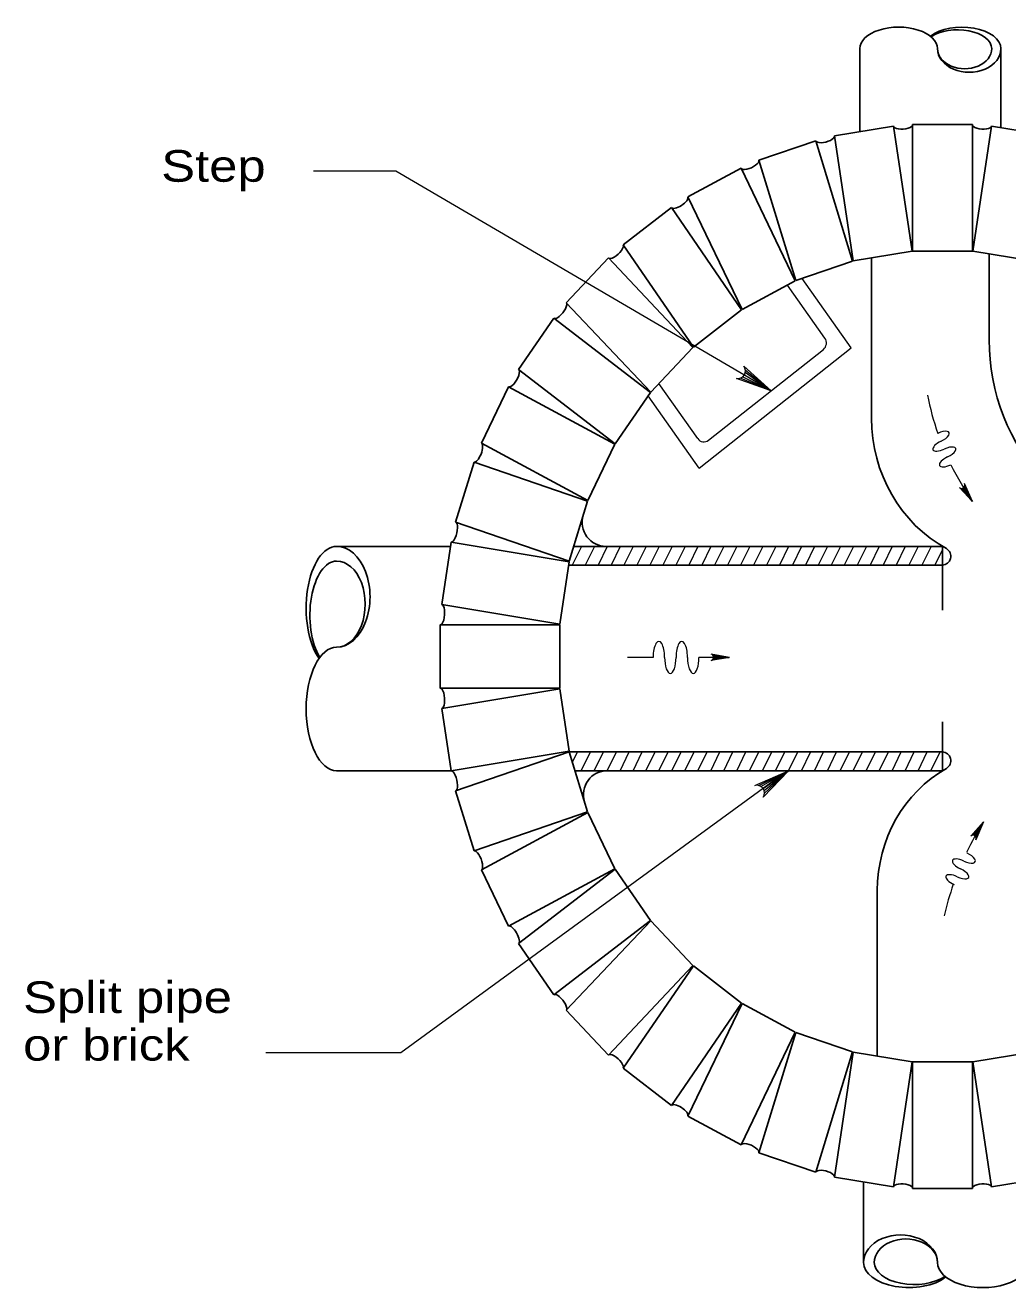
# Model space of a CAD drawing. Extents: x 1083.1 to 1117.1, y 697.4 to 741.4.
# Drawn here: x 1104.71 to 1109.55, y 723.01 to 729.25 of the extents above; entities that cross this region are included whole.
import ezdxf

# ---------------------------------------------------------------- set-up
doc = ezdxf.new("R2010")
doc.units = 0
doc.header["$LTSCALE"] = 0.062
doc.layers.add('1', color=7, linetype='Continuous', lineweight=13)

msp = doc.modelspace()

# ---------------------------------------------------------------- linework, layer by layer
at = {"layer": '1', "lineweight": 25}
for p, q in [((1108.823, 729.13192), (1108.823, 728.72233)), ((1109.51925, 729.13192), (1109.51925, 728.74242)), ((1109.08383, 728.758), (1109.08383, 728.13417)), ((1109.08383, 728.758), (1109.37842, 728.758)), ((1109.37842, 728.758), (1109.37842, 728.13417)), ((1108.69808, 728.70133), (1108.98908, 728.75017)), ((1108.69808, 728.70133), (1108.79025, 728.08517)), ((1108.98908, 728.75017), (1109.08125, 728.134)), ((1109.47317, 728.75017), (1109.381, 728.134)), ((1109.47317, 728.75017), (1109.76417, 728.70133)), ((1108.3255, 728.5815), (1108.60567, 728.67783)), ((1108.60567, 728.67783), (1108.78775, 728.08458)), ((1108.3255, 728.5815), (1108.50758, 727.98817)), ((1107.97517, 728.40133), (1108.23767, 728.543)), ((1108.23767, 728.543), (1108.50517, 727.98708)), ((1107.97517, 728.40133), (1108.24267, 727.8455)), ((1107.65583, 728.16542), (1107.89417, 728.34875)), ((1107.89417, 728.34875), (1108.2405, 727.84408)), ((1107.65583, 728.16542), (1108.00217, 727.66075)), ((1108.79025, 728.08517), (1109.08125, 728.134)), ((1109.08383, 728.13417), (1109.37842, 728.13417)), ((1109.381, 728.134), (1109.67192, 728.08517)), ((1107.37517, 727.87958), (1107.58358, 728.10008)), ((1107.58358, 728.10008), (1108.00017, 727.659)), ((1108.50758, 727.98817), (1108.78775, 728.08458)), ((1108.88108, 728.10042), (1108.88108, 727.30992)), ((1109.46125, 728.1205), (1109.46125, 727.69675)), ((1108.24267, 727.8455), (1108.50517, 727.98708)), ((1107.37517, 727.87958), (1107.79183, 727.43842)), ((1108.00217, 727.66075), (1108.2405, 727.84408)), ((1107.14033, 727.55067), (1107.3135, 727.80308)), ((1107.3135, 727.80308), (1107.79017, 727.43633)), ((1107.79183, 727.43842), (1108.00017, 727.659)), ((1107.14033, 727.55067), (1107.617, 727.184)), ((1106.95692, 727.187), (1107.09067, 727.46492)), ((1107.09067, 727.46492), (1107.61567, 727.18167)), ((1107.617, 727.184), (1107.79017, 727.43633)), ((1106.95692, 727.187), (1107.48192, 726.90375)), ((1107.48192, 726.90375), (1107.61567, 727.18167)), ((1106.8295, 726.79742), (1106.92058, 727.09408)), ((1106.92058, 727.09408), (1107.48092, 726.90125)), ((1107.38992, 726.60467), (1107.48092, 726.90125)), ((1106.8295, 726.79742), (1107.38992, 726.60467)), ((1106.76125, 726.3915), (1106.80733, 726.69958)), ((1106.80733, 726.69958), (1107.38933, 726.602)), ((1106.243, 726.678), (1106.80408, 726.678)), ((1107.41242, 726.678), (1109.23108, 726.678)), ((1109.23108, 726.678), (1109.23108, 726.36308)), ((1107.34325, 726.29392), (1107.38933, 726.602)), ((1107.38692, 726.58583), (1109.23108, 726.58583)), ((1106.76125, 726.3915), (1107.34325, 726.29392)), ((1106.75375, 725.97933), (1106.75375, 726.29125)), ((1106.75375, 726.29125), (1107.343, 726.29125)), ((1107.343, 725.97933), (1107.343, 726.29125)), ((1106.75375, 725.97933), (1107.343, 725.97933)), ((1106.76125, 725.879), (1107.34325, 725.97658)), ((1107.38933, 725.6685), (1107.34325, 725.97658)), ((1106.80733, 725.57092), (1106.76125, 725.879)), ((1109.23108, 725.81317), (1109.23108, 725.57233)), ((1106.80733, 725.57092), (1107.38933, 725.6685)), ((1106.8295, 725.47308), (1107.38992, 725.66583)), ((1107.48092, 725.36925), (1107.38992, 725.66583)), ((1107.39033, 725.6645), (1108.83858, 725.6645)), ((1108.83858, 725.6645), (1109.23108, 725.6645)), ((1106.243, 725.57233), (1106.80708, 725.57233)), ((1107.41858, 725.57233), (1108.83858, 725.57233)), ((1108.83858, 725.57233), (1109.23108, 725.57233)), ((1106.92058, 725.17642), (1106.8295, 725.47308)), ((1106.92058, 725.17642), (1107.48092, 725.36925)), ((1106.95692, 725.0835), (1107.48192, 725.36675)), ((1107.61567, 725.08883), (1107.48192, 725.36675)), ((1107.09067, 724.80558), (1106.95692, 725.0835)), ((1107.09067, 724.80558), (1107.61567, 725.08883)), ((1107.14033, 724.71983), (1107.617, 725.0865)), ((1107.79017, 724.83417), (1107.617, 725.0865)), ((1108.90933, 724.16533), (1108.90933, 724.98117)), ((1107.3135, 724.46742), (1107.79017, 724.83417)), ((1107.37525, 724.39092), (1107.79183, 724.83208)), ((1108.00017, 724.6115), (1107.79183, 724.83208)), ((1107.3135, 724.46742), (1107.14033, 724.71983)), ((1107.5835, 724.17042), (1108.00017, 724.6115)), ((1107.65583, 724.10508), (1108.00217, 724.60975)), ((1108.2405, 724.42642), (1108.00217, 724.60975)), ((1107.89417, 723.92175), (1108.2405, 724.42642)), ((1107.97517, 723.86917), (1108.24267, 724.425)), ((1108.50517, 724.28342), (1108.24267, 724.425)), ((1107.5835, 724.17042), (1107.37525, 724.39092)), ((1108.23767, 723.7275), (1108.50517, 724.28342)), ((1108.3255, 723.68908), (1108.50758, 724.28233)), ((1108.78775, 724.18592), (1108.50758, 724.28233)), ((1108.60567, 723.59267), (1108.78775, 724.18592)), ((1108.69808, 723.56917), (1108.79025, 724.18533)), ((1109.08125, 724.1365), (1108.79025, 724.18533)), ((1109.672, 724.18533), (1109.381, 724.1365)), ((1107.89417, 723.92175), (1107.65583, 724.10508)), ((1108.98908, 723.52042), (1109.08125, 724.1365)), ((1109.37842, 724.13633), (1109.08383, 724.13633)), ((1109.08383, 723.5125), (1109.08383, 724.13633)), ((1109.37842, 723.5125), (1109.37842, 724.13633)), ((1109.47317, 723.52042), (1109.381, 724.1365)), ((1108.23767, 723.7275), (1107.97517, 723.86917)), ((1108.60567, 723.59267), (1108.3255, 723.68908)), ((1108.98908, 723.52042), (1108.69808, 723.56917)), ((1108.84167, 723.148), (1108.84167, 723.54508)), ((1109.76417, 723.56917), (1109.47317, 723.52042)), ((1109.37842, 723.5125), (1109.08383, 723.5125))]:
    msp.add_line(p, q, dxfattribs=at)
at = {"layer": '1'}
for p, q in [((1108.651, 727.70508), (1108.46667, 727.96633)), ((1108.78117, 727.6565), (1108.5395, 727.99917)), ((1108.03075, 727.06333), (1108.78117, 727.6565)), ((1108.07667, 727.20108), (1108.64333, 727.64908)), ((1108.24642, 727.5145), (1108.38533, 727.44508)), ((1108.25367, 727.52333), (1108.38533, 727.44508)), ((1108.25858, 727.54925), (1108.38533, 727.44508)), ((1108.25858, 727.53717), (1108.38533, 727.44508)), ((1108.02383, 727.20925), (1107.83208, 727.481)), ((1108.23608, 727.50775), (1108.38533, 727.44508)), ((1108.03075, 727.06333), (1107.77908, 727.42017)), ((1109.37925, 726.89983), (1109.31483, 726.96917)), ((1109.37925, 726.89983), (1109.325, 726.96425)), ((1109.33142, 726.96533), (1109.37817, 726.901)), ((1109.37925, 726.89983), (1109.33758, 726.97017)), ((1109.37925, 726.89983), (1109.3395, 726.9875)), ((1109.37925, 726.89983), (1109.34033, 726.97533)), ((1109.37925, 726.89983), (1109.34042, 726.97517)), ((1107.45, 726.678), (1107.40467, 726.58583)), ((1107.51392, 726.678), (1107.4685, 726.58583)), ((1107.57783, 726.678), (1107.53242, 726.58583)), ((1107.64167, 726.678), (1107.59633, 726.58583)), ((1107.70558, 726.678), (1107.66017, 726.58583)), ((1107.7695, 726.678), (1107.72408, 726.58583)), ((1107.83333, 726.678), (1107.78792, 726.58583)), ((1107.89725, 726.678), (1107.85183, 726.58583)), ((1107.96108, 726.678), (1107.91575, 726.58583)), ((1108.025, 726.678), (1107.97958, 726.58583)), ((1108.08892, 726.678), (1108.0435, 726.58583)), ((1108.15275, 726.678), (1108.10733, 726.58583)), ((1108.21667, 726.678), (1108.17125, 726.58583)), ((1108.28058, 726.678), (1108.23517, 726.58583)), ((1108.34442, 726.678), (1108.299, 726.58583)), ((1108.40833, 726.678), (1108.36292, 726.58583)), ((1108.47217, 726.678), (1108.42683, 726.58583)), ((1108.53608, 726.678), (1108.49067, 726.58583)), ((1108.6, 726.678), (1108.55458, 726.58583)), ((1108.66383, 726.678), (1108.61842, 726.58583)), ((1108.72775, 726.678), (1108.68233, 726.58583)), ((1108.79167, 726.678), (1108.74625, 726.58583)), ((1108.8555, 726.678), (1108.81008, 726.58583)), ((1108.91942, 726.678), (1108.874, 726.58583)), ((1108.98325, 726.678), (1108.93783, 726.58583)), ((1109.04717, 726.678), (1109.00175, 726.58583)), ((1109.11108, 726.678), (1109.06567, 726.58583)), ((1109.17492, 726.678), (1109.1295, 726.58583)), ((1109.23108, 726.66233), (1109.19342, 726.58583)), ((1108.18042, 726.13083), (1108.08975, 726.14683)), ((1108.18042, 726.13083), (1108.09967, 726.1405)), ((1108.18042, 726.13083), (1108.09983, 726.1405)), ((1107.80383, 726.13083), (1107.67767, 726.13083)), ((1108.18042, 726.13083), (1108.03, 726.13083)), ((1108.18042, 726.13083), (1108.08975, 726.11483)), ((1108.18042, 726.13083), (1108.09942, 726.12083)), ((1108.18042, 726.13083), (1108.10208, 726.13517)), ((1108.10225, 726.127), (1108.17883, 726.13058)), ((1107.40583, 725.61383), (1107.43083, 725.6645)), ((1107.44925, 725.57233), (1107.49467, 725.6645)), ((1107.51317, 725.57233), (1107.55858, 725.6645)), ((1107.57708, 725.57233), (1107.62242, 725.6645)), ((1107.64092, 725.57233), (1107.68633, 725.6645)), ((1107.70483, 725.57233), (1107.75025, 725.6645)), ((1107.76867, 725.57233), (1107.81408, 725.6645)), ((1107.83258, 725.57233), (1107.878, 725.6645)), ((1107.8965, 725.57233), (1107.94192, 725.6645)), ((1107.96033, 725.57233), (1108.00575, 725.6645)), ((1108.02425, 725.57233), (1108.06967, 725.6645)), ((1108.08817, 725.57233), (1108.1335, 725.6645)), ((1108.152, 725.57233), (1108.19742, 725.6645)), ((1108.21592, 725.57233), (1108.26133, 725.6645)), ((1108.27975, 725.57233), (1108.32517, 725.6645)), ((1108.34367, 725.57233), (1108.38908, 725.6645)), ((1108.40758, 725.57233), (1108.45292, 725.6645)), ((1108.47142, 725.57233), (1108.51683, 725.6645)), ((1108.53533, 725.57233), (1108.5805, 725.664)), ((1108.59917, 725.57233), (1108.64458, 725.6645)), ((1108.66308, 725.57233), (1108.7085, 725.6645)), ((1108.727, 725.57233), (1108.77242, 725.6645)), ((1108.79083, 725.57233), (1108.83625, 725.6645)), ((1108.85475, 725.57233), (1108.90017, 725.6645)), ((1108.85475, 725.57233), (1108.89992, 725.664)), ((1108.91867, 725.57233), (1108.964, 725.6645)), ((1108.9825, 725.57233), (1109.02792, 725.6645)), ((1109.04642, 725.57233), (1109.09183, 725.6645)), ((1109.11033, 725.57233), (1109.15567, 725.6645)), ((1109.17417, 725.57233), (1109.21958, 725.6645)), ((1108.32458, 725.49933), (1108.47142, 725.57233)), ((1108.33558, 725.49442), (1108.47142, 725.57233)), ((1108.34617, 725.48425), (1108.47142, 725.57233)), ((1108.35133, 725.474), (1108.47142, 725.57233)), ((1108.35325, 725.46183), (1108.47142, 725.57233)), ((1109.4335, 725.32025), (1109.37092, 725.249)), ((1109.4335, 725.32025), (1109.38133, 725.25425)), ((1109.4335, 725.32025), (1109.3815, 725.25433)), ((1109.4335, 725.32025), (1109.38692, 725.25342)), ((1109.39342, 725.24908), (1109.43283, 725.31867)), ((1109.4335, 725.32025), (1109.39608, 725.23133)), ((1109.4335, 725.32025), (1109.39667, 725.24317))]:
    msp.add_line(p, q, dxfattribs=at)
for points in [[(1108.38533, 727.44508), (1106.53542, 728.528), (1106.12867, 728.528)], [(1108.25125, 727.566), (1108.38533, 727.44508), (1108.21508, 727.50508)], [(1108.446, 725.557), (1106.56008, 724.18133), (1105.8945, 724.18133)], [(1108.30625, 725.4995), (1108.47142, 725.57233), (1108.347, 725.44158)]]:
    msp.add_lwpolyline(points, dxfattribs=at)
for centre, start, end in [((1108.22084, 727.54282), 261.36559, 37.19171), ((1108.31498, 725.46228), 327.19941, 103.02554)]:
    msp.add_arc(centre, 0.0382, start, end, dxfattribs=at)
at = {"layer": '1', "lineweight": 25}
for centre, start, end in [((1107.57206, 726.79599), 162.93825, 270), ((1107.57826, 725.45434), 90, 197.06204)]:
    msp.add_arc(centre, 0.118, start, end, dxfattribs=at)
for centre, major_axis, ratio, start_param, end_param in [((1109.01477, 729.13189), (0.19174, 0), 0.553681, 0, 3.1415927), ((1109.32751, 729.13189), (0.19174, 0), 0.553681, 0, 2.5244674), ((1109.30532, 729.13189), (0.16853, 0), 0.553681, 0, 2.4601045), ((1109.34018, 729.13189), (0.13367, 0), 0.743645, 3.1415928, 6.2831855), ((1109.36288, 729.13189), (0.15637, 0), 0.743645, 3.1415928, 6.2831855), ((1109.03643, 728.75408), (0.04736, 0.00403), 0.392063, 3.1374537, 6.2790464), ((1109.42579, 728.75408), (0.04736, -0.00402), 0.392063, 3.1457278, 6.2873205), ((1108.65187, 728.68959), (0.04614, 0.01196), 0.389745, 3.1296802, 6.2712729), ((1108.28158, 728.56221), (0.04376, 0.01956), 0.385425, 3.1233154, 6.2649081), ((1107.93466, 728.37507), (0.04029, 0.02663), 0.37966, 3.1190216, 6.2606142), ((1107.61967, 728.13278), (0.03583, 0.033), 0.373134, 3.117142, 6.2587347), ((1107.34436, 727.8413), (0.03052, 0.03853), 0.366547, 3.1177098, 6.2593025), ((1110.39145, 727.69675), (0, 0.98483), 0.944544, 1.5707933, 3.1415918), ((1107.1155, 727.50782), (0.0245, 0.04308), 0.360527, 3.1205104, 6.2621031), ((1109.56493, 727.30989), (0, -0.72403), 0.944544, 4.7123884, 5.8053598), ((1106.93874, 727.14054), (0.01791, 0.04658), 0.355581, 3.1251606, 6.2667532), ((1106.81842, 726.7485), (0.01091, 0.04895), 0.352085, 3.1311777, 6.2727704), ((1106.243, 726.37349), (0, 0.30449), 0.493973, 6.2831853, 8.8076526), ((1106.243, 726.42966), (0, 0.24833), 0.663452, 3.1415925, 6.2831852), ((1109.23105, 726.629), (0, -0.04315), 0.944544, 0.0006242, 2.6457264), ((1106.243, 726.33825), (0, 0.26763), 0.493973, 6.2831853, 8.7432897), ((1106.243, 726.3936), (0, 0.21228), 0.663452, 3.1415925, 6.2831852), ((1106.75751, 726.34136), (0.00366, 0.05015), 0.350278, 3.1380288, 6.2796215), ((1106.243, 725.87683), (0, 0.30449), 0.493973, 6.2831853, 9.4247779), ((1106.75751, 725.92915), (-0.00367, 0.05015), 0.350278, 3.1451597, 6.2867524), ((1109.23107, 725.62151), (0, 0.04297), 0.944544, 3.6464672, 6.2827998), ((1109.55476, 724.98115), (0, 0.68332), 0.944544, 0.4905201, 1.5707908), ((1106.81842, 725.52201), (-0.01091, 0.04895), 0.352086, 3.1520106, 6.2936033), ((1106.93873, 725.12998), (-0.01791, 0.04658), 0.355583, 3.1580272, 6.2996199), ((1107.11549, 724.76269), (-0.0245, 0.04308), 0.360529, 3.1626767, 6.3042693), ((1107.34435, 724.42921), (-0.03053, 0.03852), 0.36655, 3.1654763, 6.307069), ((1107.61966, 724.13773), (-0.03584, 0.033), 0.373137, 3.166043, 6.3076357), ((1107.93466, 723.89543), (-0.04029, 0.02663), 0.379662, 3.1641623, 6.3057549), ((1108.28157, 723.70829), (-0.04376, 0.01956), 0.385427, 3.1598674, 6.3014601), ((1108.65187, 723.58091), (-0.04614, 0.01196), 0.389747, 3.1535017, 6.2950944), ((1109.03642, 723.51643), (-0.04736, 0.00402), 0.392063, 3.1457278, 6.2873205), ((1109.42578, 723.51643), (-0.04736, -0.00403), 0.392063, 3.1374537, 6.2790464), ((1109.02407, 723.14797), (-0.18243, 0), 0.743645, 3.1415928, 6.2831855), ((1109.05055, 723.14797), (-0.15595, 0), 0.743645, 3.1415928, 6.2831855), ((1109.06533, 723.14797), (-0.2237, 0), 0.553681, 0, 2.5244674), ((1109.09122, 723.14797), (-0.19662, 0), 0.553681, 0, 2.4601045), ((1109.4302, 723.14797), (-0.2237, 0), 0.553681, 0, 3.1415927)]:
    msp.add_ellipse(centre, major_axis=major_axis, ratio=ratio, start_param=start_param, end_param=end_param, dxfattribs=at)
at = {"layer": '1'}
for centre, major_axis, ratio, start_param, end_param in [((1108.62074, 727.68113), (0, -0.03998), 0.944544, 0.6413781, 2.2121698), ((1110.39145, 727.69675), (0, 1.3355), 0.944544, 1.7766136, 1.9236264), ((1108.05405, 727.23315), (0, -0.03998), 0.944544, 5.3537624, 6.9245643), ((1109.21581, 727.21591), (0.0479, 0.02288), 0.394857, 4.6926325, 7.8342252), ((1109.23197, 727.17719), (0.0479, 0.02288), 0.394857, 1.5510399, 4.6926325), ((1109.24814, 727.13847), (0.0479, 0.02288), 0.394857, 4.6926325, 7.8342252), ((1109.26431, 727.09975), (0.0479, 0.02288), 0.394857, 1.5510399, 4.6926325), ((1110.39145, 727.69675), (0, 1.3355), 0.944544, 2.0505118, 2.2102187), ((1109.32581, 726.9804), (0, -0.01618), 0.944544, 5.477695, 8.3116647), ((1107.83212, 726.13084), (0, -0.07867), 0.359358, 1.5707963, 4.712389), ((1107.94521, 726.13084), (0, -0.07867), 0.359358, 1.5707963, 4.712389), ((1108.0874, 726.13085), (0, -0.01618), 0.944544, 0.1533668, 2.9873365), ((1107.88866, 726.13084), (0, -0.07867), 0.359358, 4.712389, 7.8539816), ((1108.00175, 726.13084), (0, -0.07867), 0.359358, 4.712389, 7.8539816), ((1110.58476, 724.5014), (0, -1.46838), 0.944544, 4.1208628, 4.2402335), ((1109.38219, 725.2381), (0, -0.01618), 0.944544, 1.1399744, 3.9739441), ((1109.34442, 725.14629), (0.04794, -0.02278), 0.394921, 4.7320843, 7.873677), ((1109.32832, 725.10754), (0.04794, -0.02278), 0.394921, 1.5904917, 4.7320843), ((1109.31222, 725.06879), (0.04794, -0.02278), 0.394921, 4.7320843, 7.873677), ((1109.29611, 725.03003), (0.04794, -0.02278), 0.394921, 1.5904917, 4.7320843), ((1110.58476, 724.5014), (0, -1.46837), 0.944544, 4.3571696, 4.467435)]:
    msp.add_ellipse(centre, major_axis=major_axis, ratio=ratio, start_param=start_param, end_param=end_param, dxfattribs=at)

# ---------------------------------------------------------------- texts
at = {"layer": '1', "width": 1.2}
for s, p in [('Step', (1105.37783, 728.47575)), ('Split pipe', (1104.69675, 724.37783)), ('or brick', (1104.69675, 724.14317))]:
    msp.add_text(s, height=0.156, dxfattribs=at).set_placement(p)

doc.saveas('drawing.dxf')
